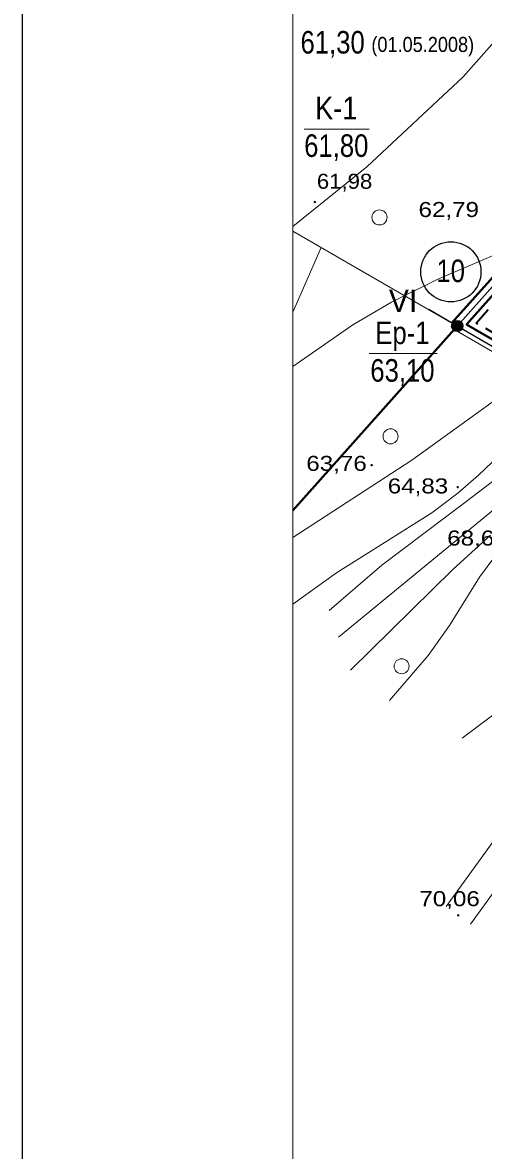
# Model space of a CAD drawing. Extents: x 628176 to 629009, y 6439913 to 6440496.
# Drawn here: x 628178.3 to 628239.5, y 6440112.2 to 6440262.2 of the extents above; entities that cross this region are included whole.
import ezdxf
from ezdxf.enums import TextEntityAlignment as Align

# ---------------------------------------------------------------- set-up
doc = ezdxf.new("R2010")
doc.units = 0
doc.header["$LTSCALE"] = 0.8
doc.linetypes.add('MEDIUM_DASHED', pattern=[4.5, 3, -1.5])
for name, color, linetype, lineweight in [('1', 7, 'Continuous', 13), ('10', 7, 'Continuous', 25), ('11', 7, 'Continuous', 13), ('12', 7, 'Continuous', 13), ('14', 7, 'Continuous', 25), ('20', 7, 'Continuous', 40), ('21', 7, 'MEDIUM_DASHED', 35), ('3', 7, 'Continuous', 13), ('50', 7, 'Continuous', 13), ('6', 7, 'Continuous', 13)]:
    doc.layers.add(name, color=color, linetype=linetype, lineweight=lineweight)

msp = doc.modelspace()

# ---------------------------------------------------------------- hatches: boundary and pattern name
at = {"layer": '1'}
for points in [[(628217.2014, 6440238.3196, 1), (628217.0014, 6440238.3196, 1)], [(628224.7504, 6440203.3308, 1), (628224.5504, 6440203.3308, 1)], [(628236.1967, 6440200.3961, 1), (628235.9967, 6440200.3961, 1)], [(628236.2553, 6440143.4341, 1), (628236.0553, 6440143.4341, 1)]]:
    msp.add_hatch(color=256, dxfattribs=at).paths.add_polyline_path(points)
at = {"layer": '10'}
msp.add_hatch(color=256, dxfattribs=at).paths.add_polyline_path([(628236.7725, 6440221.8318, 1), (628235.2725, 6440221.8318, 1)])

# ---------------------------------------------------------------- linework, layer by layer
at = {"layer": '1'}
for p, q in [((628234.54, 6440144.61), (628250.4, 6440166.54)), ((628237.77, 6440142.26), (628253.73, 6440164.32))]:
    msp.add_line(p, q, dxfattribs=at)
for centre, radius in [((628217.1014, 6440238.3196), 0.1), ((628225.6943, 6440236.2775), 1), ((628227.1627, 6440207.1544), 1), ((628224.6504, 6440203.3308), 0.1), ((628236.0967, 6440200.3961), 0.1), ((628228.6311, 6440176.5629), 1), ((628236.1553, 6440143.4341), 0.1)]:
    msp.add_circle(centre, radius, dxfattribs=at)
at = {"layer": '10'}
for centre, radius in [((628235.178, 6440229.0379), 4), ((628236.0225, 6440221.8318), 0.75)]:
    msp.add_circle(centre, radius, dxfattribs=at)
at = {"layer": '11'}
msp.add_lwpolyline([(628497.5, 6440118.54), (628474.19, 6440080.39), (628272.25, 6440200.89), (628236.02, 6440221.83), (628393.19, 6440398.39)], dxfattribs=at)
at = {"layer": '12'}
for p, q in [((628215.67, 6440248.04), (628224.3, 6440248.04)), ((628224.32, 6440218.19), (628233.35, 6440218.19))]:
    msp.add_line(p, q, dxfattribs=at)
at = {"layer": '14'}
msp.add_lwpolyline([(628267.86, 6440203.3), (628236.02, 6440221.83), (628232.27, 6440224.02)], dxfattribs=at)
at = {"layer": '20'}
for p, q in [((628235.32, 6440222.24), (628409.42, 6440417.82)), ((628214.18, 6440197.29), (628236.02, 6440221.83))]:
    msp.add_line(p, q, dxfattribs=at)
at = {"layer": '21', "linetype": 'Continuous', "lineweight": 40}
msp.add_lwpolyline([(628320.39, 6440173.09), (628272.66, 6440201.58), (628237.27, 6440222.03), (628393.6, 6440397.65)], dxfattribs=at)
at = {"layer": '21'}
msp.add_lwpolyline([(628321.72, 6440173.24), (628273.06, 6440202.27), (628238.52, 6440222.23), (628394.01, 6440396.91)], dxfattribs=at)
at = {"layer": '3'}
for p, q in [((628214.18, 6440235.09), (628224, 6440243)), ((628222.14, 6440222), (628214.18, 6440216.43)), ((628230, 6440204), (628214.18, 6440193.68)), ((628241.6, 6440198), (628220.23, 6440180.45)), ((628235.42, 6440189.43), (628240.44, 6440194)), ((628226, 6440190), (628219, 6440184)), ((628235.42, 6440189.43), (628221.85, 6440176.06)), ((628220, 6440189), (628214.18, 6440184.84))]:
    msp.add_line(p, q, dxfattribs=at)
for points in [[(628224, 6440243), (628236.8, 6440255), (628243, 6440262)], [(628245.18, 6440233), (628240.78, 6440231.22), (628233.35, 6440228), (628227.28, 6440225), (628222.14, 6440222)], [(628261.69, 6440229), (628260, 6440227.39), (628253.37, 6440221.56), (628244.49, 6440214.43), (628230, 6440204)], [(628249.17, 6440212), (628243.37, 6440206.27), (628238.83, 6440202), (628236.1, 6440199.6), (628232.65, 6440197), (628220, 6440189)], [(628244.68, 6440204), (628241.81, 6440202), (628237, 6440198.3), (628226, 6440190)], [(628244, 6440193.83), (628243.43, 6440193.51), (628242.5, 6440192.75), (628241.17, 6440191.34), (628239, 6440188.44), (628235, 6440182), (628232.14, 6440178), (628227, 6440172)], [(628258.78, 6440176.84), (628256, 6440176.84), (628251, 6440176), (628246, 6440174), (628242, 6440171), (628236.67, 6440167)]]:
    msp.add_lwpolyline(points, dxfattribs=at)
at = {"layer": '50', "lineweight": 25}
msp.add_lwpolyline([(628178.27, 6440495.9), (629008.51, 6440495.9), (629008.51, 6439918.47), (628178.27, 6439918.47)], close=True, dxfattribs=at)
at = {"layer": '50'}
msp.add_lwpolyline([(628214.18, 6440472.45), (628760.23, 6440472.45), (628760.23, 6440028.67), (628214.18, 6440028.67)], close=True, dxfattribs=at)
at = {"layer": '6'}
for p, q in [((628236.02, 6440221.83), (628214.18, 6440234.46)), ((628217.94, 6440232.29), (628214.18, 6440223.69))]:
    msp.add_line(p, q, dxfattribs=at)
msp.add_lwpolyline([(628473.77, 6440079.94), (628271.95, 6440200.37), (628235.6, 6440221.38)], dxfattribs=at)

# ---------------------------------------------------------------- texts
at = {"layer": '1'}
for s, width, p in [('61,98', 1.1, (628217.37, 6440240.09)), ('62,79', 1.2, (628230.88, 6440236.33)), ('63,76', 1.2, (628215.97, 6440202.56)), ('64,83', 1.2, (628226.79, 6440199.56)), ('68,63', 1.2, (628234.69, 6440192.63)), ('70,06', 1.2, (628230.99, 6440144.65))]:
    msp.add_text(s, height=2, dxfattribs=dict(at, width=width)).set_placement(p)
at = {"layer": '10', "width": 0.85}
msp.add_text('10', height=3, dxfattribs=at).set_placement((628235.15, 6440227.67), align=Align.CENTER)
at = {"layer": '12'}
for s, height, width, p in [('61,30', 3, 0.85, (628219.465, 6440258.08)), ('(01.05.2008)', 2, 0.9, (628231.44, 6440258.29)), ('K-1', 3, 0.9, (628219.945, 6440249.33)), ('61,80', 3, 0.85, (628219.95, 6440244.33)), ('Ep-1', 3, 0.85, (628228.74, 6440219.43)), ('63,10', 3, 0.85, (628228.74, 6440214.43))]:
    msp.add_text(s, height=height, dxfattribs=dict(at, width=width)).set_placement(p, align=Align.CENTER)
at = {"layer": '14'}
msp.add_text('VI', height=3, dxfattribs=at).set_placement((628228.83, 6440223.69), align=Align.CENTER)

doc.saveas('drawing.dxf')
